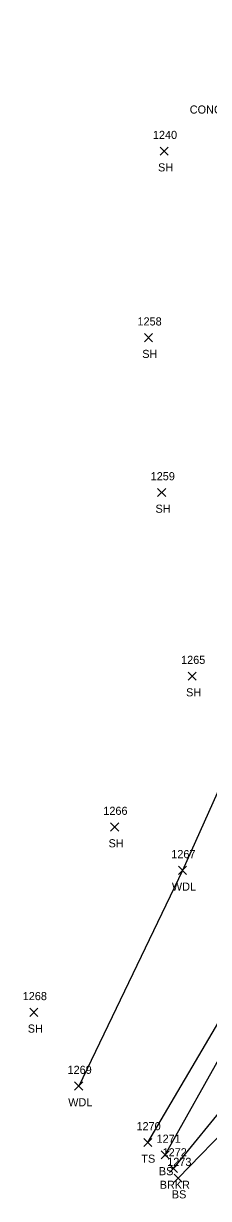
# Model space of a CAD drawing. Extents: x 1651305 to 1654558, y 539481 to 548441.
# Drawn here: x 1654205.7 to 1654251.1, y 544458.6 to 544748.1 of the extents above; entities that cross this region are included whole.
import ezdxf

# ---------------------------------------------------------------- set-up
doc = ezdxf.new("R2010")
doc.units = 0
for name, color, linetype in [('L_A', 7, 'Continuous'), ('L_I', 7, 'Continuous'), ('L_TIC', 7, 'Continuous'), ('LAWA', 7, 'Continuous'), ('LAWE', 7, 'Continuous'), ('LELB', 7, 'Continuous'), ('S_C', 7, 'Continuous')]:
    doc.layers.add(name, color=color, linetype=linetype)

msp = doc.modelspace()

# ---------------------------------------------------------------- linework, layer by layer
at = {"layer": 'L_TIC'}
for points in [[(1654239.22, 544715.62), (1654241.22, 544717.62)], [(1654241.22, 544715.62), (1654239.22, 544717.62)], [(1654235.34, 544669.67), (1654237.34, 544671.67)], [(1654237.34, 544669.67), (1654235.34, 544671.67)], [(1654238.59, 544631.53), (1654240.59, 544633.53)], [(1654240.59, 544631.53), (1654238.59, 544633.53)], [(1654246.11, 544586.29), (1654248.11, 544588.29)], [(1654248.11, 544586.29), (1654246.11, 544588.29)], [(1654227.06, 544549.1), (1654229.06, 544551.1)], [(1654229.06, 544549.1), (1654227.06, 544551.1)], [(1654243.7, 544538.43), (1654245.7, 544540.43)], [(1654245.7, 544538.43), (1654243.7, 544540.43)], [(1654207.19, 544503.45), (1654209.19, 544505.45)], [(1654209.19, 544503.45), (1654207.19, 544505.45)], [(1654218.21, 544485.29), (1654220.21, 544487.29)], [(1654220.21, 544485.29), (1654218.21, 544487.29)], [(1654235.19, 544471.4), (1654237.19, 544473.4)], [(1654237.19, 544471.4), (1654235.19, 544473.4)], [(1654239.47, 544468.32), (1654241.47, 544470.32)], [(1654241.47, 544468.32), (1654239.47, 544470.32)], [(1654241.51, 544464.97), (1654243.51, 544466.97)], [(1654243.51, 544464.97), (1654241.51, 544466.97)], [(1654242.66, 544462.61), (1654244.66, 544464.61)], [(1654244.66, 544462.61), (1654242.66, 544464.61)]]:
    msp.add_lwpolyline(points, dxfattribs=at)
at = {"layer": 'LAWA'}
msp.add_lwpolyline([(1654297.61, 544656.98), (1654285.27, 544643.74), (1654278.09, 544612.04), (1654262.46, 544579.16), (1654244.7, 544539.43), (1654219.21, 544486.29)], dxfattribs=at)
at = {"layer": 'LAWE'}
msp.add_lwpolyline([(1654242.51, 544465.97), (1654256.87, 544483.55), (1654283.12, 544539.87), (1654291.83, 544564.24), (1654301.76, 544593.78), (1654310.98, 544627.69), (1654314.7, 544654.65), (1654333.85, 544703.3), (1654340.89, 544719.25), (1654343, 544745.95), (1654343.54, 544777), (1654341.26, 544814.62), (1654342.7, 544842.64), (1654342.65, 544866.8)], dxfattribs=at)
at = {"layer": 'LELB'}
for points in [[(1654243.66, 544463.61), (1654257.64, 544478.05), (1654284.35, 544538.42), (1654294.46, 544561.39), (1654312.81, 544626.03), (1654318.85, 544643.27), (1654339.17, 544696.64), (1654344.53, 544715.65), (1654345.59, 544746.87), (1654345.75, 544776.72), (1654344.63, 544815.2), (1654344.44, 544841.84), (1654343.53, 544866.97)], [(1654236.19, 544472.4), (1654254.47, 544503.5), (1654271.69, 544523.85), (1654289.21, 544566.35), (1654298.06, 544598.76)], [(1654240.47, 544469.32), (1654255.46, 544496.13), (1654283.12, 544539.87)]]:
    msp.add_lwpolyline(points, dxfattribs=at)

# ---------------------------------------------------------------- texts
at = {"layer": 'L_A'}
for s, p in [('SH', (1654238.71, 544711.62)), ('SH', (1654234.83, 544665.67)), ('SH', (1654238.08, 544627.53)), ('SH', (1654245.6, 544582.29)), ('SH', (1654226.55, 544545.1)), ('WDL', (1654242.11, 544534.43)), ('SH', (1654206.68, 544499.45)), ('WDL', (1654216.62, 544481.29)), ('TS', (1654234.6, 544467.4)), ('BS', (1654238.91, 544464.32)), ('BRKR', (1654239.11, 544460.97)), ('BS', (1654242.1, 544458.61))]:
    msp.add_text(s, height=2, dxfattribs=at).set_placement(p)
at = {"layer": 'L_I'}
for s, p in [('1240', (1654237.44, 544719.62)), ('1258', (1654233.65, 544673.67)), ('1259', (1654236.89, 544635.53)), ('1265', (1654244.37, 544590.29)), ('1266', (1654225.26, 544553.1)), ('1267', (1654241.96, 544542.43)), ('1268', (1654205.45, 544507.45)), ('1269', (1654216.46, 544489.29)), ('1270', (1654233.41, 544475.4)), ('1271', (1654238.34, 544472.32)), ('1272', (1654239.82, 544468.97)), ('1273', (1654240.96, 544466.61))]:
    msp.add_text(s, height=2, dxfattribs=at).set_placement(p)
at = {"layer": 'S_C'}
msp.add_text('CONCRETE UNDERGROUND TELEPHONE', height=2, dxfattribs=at).set_placement((1654246.5, 544725.87))

doc.saveas('drawing.dxf')
